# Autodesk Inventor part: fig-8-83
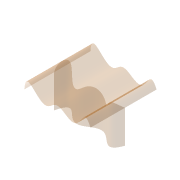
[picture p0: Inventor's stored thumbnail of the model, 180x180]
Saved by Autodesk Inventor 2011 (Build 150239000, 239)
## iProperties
Shininess: 64.0
Length Units: 11269
Angle Units: 11279
Time Units: 11290
Mass Units: 11283
Length Display Precision: 3
Angle Display Precision: 2
Compacted: True
Part Number: fig-8-83
Document SubType Name: Modeling
Created: 2003-08
Designer: Owner
Manufacturer: Standard
Standards Organization: Custom
Density: 1 g/cm^3
Density: 0.0
Volumn: 0.0
Area: 0.0
PropertySet Name: Model Information
Control State: 0
Master: False
Checked Out: False
Author: Owner
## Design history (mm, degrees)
sketch "Sketch1"
  geometry: 7 further points
  constraints: 7 other
  dimensions: "d0" = 80 horizontal distance of point (40, 1.742) point (-40, -4.065); "d1" = 40 horizontal distance of point (0, 0) point (-40, -4.065)
extrude_surface "ExtrusionSrf1" sketch "Sketch1" dims "d2" = 80, "d3" = 0
sketch "Sketch2"
  geometry: L1 (40, 0)-(40, -40) reference; L2 (-40, 0)-(-40, -40) reference; 7 further points
  constraints: 2 point on line, 7 other
extrude_surface "ExtrusionSrf2" sketch "Sketch2" dims "d4" = 80, "d5" = 0
sketch "Sketch3"
  geometry: 2 further points
  constraints: 4 other
sketch "Sketch4"
  geometry: L1 (52.956, 12.425)-(-10.974, 12.425); A1 r 27.841 centre (-10.974, -15.416) between (-10.974, 12.425) and (-7.259, -43.008)
  constraints: 2 end point, 2 point on circle, 1 centre point, 1 horizontal, 1 tangent
feature "Trim1"
body "Srf1"
body "Srf2"
